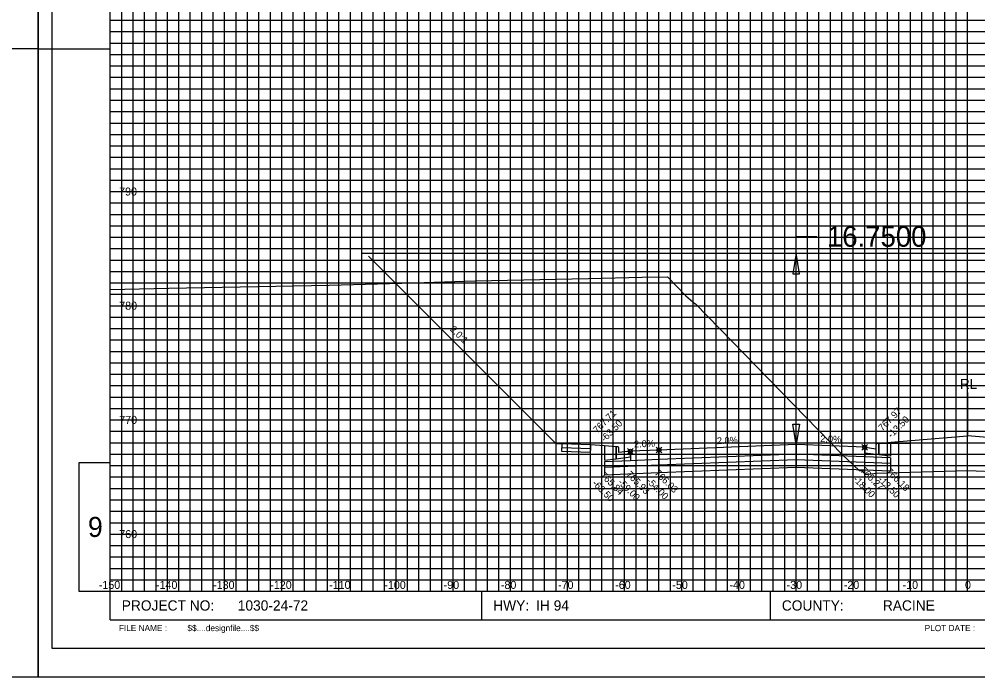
# Model space of a CAD drawing. Extents: x 578243 to 601557, y 174899 to 175559.
# Drawn here: x 600533.9 to 600701.6, y 174898.8 to 175014 of the extents above; entities that cross this region are included whole.
import ezdxf

# ---------------------------------------------------------------- set-up
doc = ezdxf.new("R2010")
doc.units = 0
for name, color, linetype in [('E_PROF_Grid', 7, 'Continuous'), ('E_PROF_GridMin', 7, 'Continuous'), ('P_CRDR_Label', 7, 'Continuous'), ('P_CRDR_Link', 7, 'Continuous'), ('P_E_XS_Ground', 7, 'Continuous'), ('P_RW_SlopeIntercepts', 7, 'Continuous'), ('P_XS_Text', 7, 'Continuous'), ('PLT_Sheet_Border', 7, 'Continuous'), ('PLT_Sheet_Info', 7, 'Continuous')]:
    doc.layers.add(name, color=color, linetype=linetype)

msp = doc.modelspace()

# ---------------------------------------------------------------- linework, layer by layer
at = {"layer": 'E_PROF_Grid'}
for p, q in [((600559.84, 174913.8), (600559.84, 175108.8)), ((600569.84, 174913.8), (600569.84, 175108.8)), ((600579.84, 174913.8), (600579.84, 175108.8)), ((600589.84, 174913.8), (600589.84, 175108.8)), ((600599.84, 174913.8), (600599.84, 175108.8)), ((600609.84, 174913.8), (600609.84, 175108.8)), ((600619.84, 174913.8), (600619.84, 175108.8)), ((600629.84, 174913.8), (600629.84, 175108.8)), ((600639.84, 174913.8), (600639.84, 175108.8)), ((600649.84, 174913.8), (600649.84, 175108.8)), ((600659.84, 174913.8), (600659.84, 175108.8)), ((600669.84, 174913.8), (600669.84, 175108.8)), ((600679.84, 174913.8), (600679.84, 175108.8)), ((600689.84, 174913.8), (600689.84, 175108.8)), ((600699.84, 174913.8), (600699.84, 175108.8)), ((600549.84, 175013.8), (600864.84, 175013.8)), ((600549.84, 175003.8), (600864.84, 175003.8)), ((600549.84, 174993.8), (600864.84, 174993.8)), ((600549.84, 174983.8), (600864.84, 174983.8)), ((600549.84, 174973.8), (600864.84, 174973.8)), ((600549.84, 174963.8), (600864.84, 174963.8)), ((600549.84, 174953.8), (600864.84, 174953.8)), ((600549.84, 174943.8), (600864.84, 174943.8)), ((600549.84, 174933.8), (600864.84, 174933.8)), ((600549.84, 174923.8), (600864.84, 174923.8))]:
    msp.add_line(p, q, dxfattribs=at)
at = {"layer": 'E_PROF_GridMin'}
for p, q in [((600551.84, 174913.8), (600551.84, 175108.8)), ((600553.84, 174913.8), (600553.84, 175108.8)), ((600555.84, 174913.8), (600555.84, 175108.8)), ((600557.84, 174913.8), (600557.84, 175108.8)), ((600561.84, 174913.8), (600561.84, 175108.8)), ((600563.84, 174913.8), (600563.84, 175108.8)), ((600565.84, 174913.8), (600565.84, 175108.8)), ((600567.84, 174913.8), (600567.84, 175108.8)), ((600571.84, 174913.8), (600571.84, 175108.8)), ((600573.84, 174913.8), (600573.84, 175108.8)), ((600575.84, 174913.8), (600575.84, 175108.8)), ((600577.84, 174913.8), (600577.84, 175108.8)), ((600581.84, 174913.8), (600581.84, 175108.8)), ((600583.84, 174913.8), (600583.84, 175108.8)), ((600585.84, 174913.8), (600585.84, 175108.8)), ((600587.84, 174913.8), (600587.84, 175108.8)), ((600591.84, 174913.8), (600591.84, 175108.8)), ((600593.84, 174913.8), (600593.84, 175108.8)), ((600595.84, 174913.8), (600595.84, 175108.8)), ((600597.84, 174913.8), (600597.84, 175108.8)), ((600601.84, 174913.8), (600601.84, 175108.8)), ((600603.84, 174913.8), (600603.84, 175108.8)), ((600605.84, 174913.8), (600605.84, 175108.8)), ((600607.84, 174913.8), (600607.84, 175108.8)), ((600611.84, 174913.8), (600611.84, 175108.8)), ((600613.84, 174913.8), (600613.84, 175108.8)), ((600615.84, 174913.8), (600615.84, 175108.8)), ((600617.84, 174913.8), (600617.84, 175108.8)), ((600621.84, 174913.8), (600621.84, 175108.8)), ((600623.84, 174913.8), (600623.84, 175108.8)), ((600625.84, 174913.8), (600625.84, 175108.8)), ((600627.84, 174913.8), (600627.84, 175108.8)), ((600631.84, 174913.8), (600631.84, 175108.8)), ((600633.84, 174913.8), (600633.84, 175108.8)), ((600635.84, 174913.8), (600635.84, 175108.8)), ((600637.84, 174913.8), (600637.84, 175108.8)), ((600641.84, 174913.8), (600641.84, 175108.8)), ((600643.84, 174913.8), (600643.84, 175108.8)), ((600645.84, 174913.8), (600645.84, 175108.8)), ((600647.84, 174913.8), (600647.84, 175108.8)), ((600651.84, 174913.8), (600651.84, 175108.8)), ((600653.84, 174913.8), (600653.84, 175108.8)), ((600655.84, 174913.8), (600655.84, 175108.8)), ((600657.84, 174913.8), (600657.84, 175108.8)), ((600661.84, 174913.8), (600661.84, 175108.8)), ((600663.84, 174913.8), (600663.84, 175108.8)), ((600665.84, 174913.8), (600665.84, 175108.8)), ((600667.84, 174913.8), (600667.84, 175108.8)), ((600671.84, 174913.8), (600671.84, 175108.8)), ((600673.84, 174913.8), (600673.84, 175108.8)), ((600675.84, 174913.8), (600675.84, 175108.8)), ((600677.84, 174913.8), (600677.84, 175108.8)), ((600681.84, 174913.8), (600681.84, 175108.8)), ((600683.84, 174913.8), (600683.84, 175108.8)), ((600685.84, 174913.8), (600685.84, 175108.8)), ((600687.84, 174913.8), (600687.84, 175108.8)), ((600691.84, 174913.8), (600691.84, 175108.8)), ((600693.84, 174913.8), (600693.84, 175108.8)), ((600695.84, 174913.8), (600695.84, 175108.8)), ((600697.84, 174913.8), (600697.84, 175108.8)), ((600549.84, 175011.8), (600864.84, 175011.8)), ((600549.84, 175009.8), (600864.84, 175009.8)), ((600549.84, 175007.8), (600864.84, 175007.8)), ((600549.84, 175005.8), (600864.84, 175005.8)), ((600549.84, 175001.8), (600864.84, 175001.8)), ((600549.84, 174999.8), (600864.84, 174999.8)), ((600549.84, 174997.8), (600864.84, 174997.8)), ((600549.84, 174995.8), (600864.84, 174995.8)), ((600549.84, 174991.8), (600864.84, 174991.8)), ((600549.84, 174989.8), (600864.84, 174989.8)), ((600549.84, 174987.8), (600864.84, 174987.8)), ((600549.84, 174985.8), (600864.84, 174985.8)), ((600549.84, 174981.8), (600864.84, 174981.8)), ((600549.84, 174979.8), (600864.84, 174979.8)), ((600549.84, 174977.8), (600864.84, 174977.8)), ((600549.84, 174975.8), (600864.84, 174975.8)), ((600549.84, 174971.8), (600864.84, 174971.8)), ((600549.84, 174969.8), (600864.84, 174969.8)), ((600549.84, 174967.8), (600864.84, 174967.8)), ((600549.84, 174965.8), (600864.84, 174965.8)), ((600549.84, 174961.8), (600864.84, 174961.8)), ((600549.84, 174959.8), (600864.84, 174959.8)), ((600549.84, 174957.8), (600864.84, 174957.8)), ((600549.84, 174955.8), (600864.84, 174955.8)), ((600549.84, 174951.8), (600864.84, 174951.8)), ((600549.84, 174949.8), (600864.84, 174949.8)), ((600549.84, 174947.8), (600864.84, 174947.8)), ((600549.84, 174945.8), (600864.84, 174945.8)), ((600549.84, 174941.8), (600864.84, 174941.8)), ((600549.84, 174939.8), (600864.84, 174939.8)), ((600549.84, 174937.8), (600864.84, 174937.8)), ((600549.84, 174935.8), (600864.84, 174935.8)), ((600549.84, 174931.8), (600864.84, 174931.8)), ((600549.84, 174929.8), (600864.84, 174929.8)), ((600549.84, 174927.8), (600864.84, 174927.8)), ((600549.84, 174925.8), (600864.84, 174925.8)), ((600549.84, 174921.8), (600864.84, 174921.8)), ((600549.84, 174919.8), (600864.84, 174919.8)), ((600549.84, 174917.8), (600864.84, 174917.8)), ((600549.84, 174915.8), (600864.84, 174915.8)), ((600537.19, 174898.8), (600537.19, 174908.8)), ((600527.19, 174898.8), (600537.19, 174898.8))]:
    msp.add_line(p, q, dxfattribs=at)
at = {"layer": 'P_CRDR_Label'}
for points in [[(600699.84, 174948.61), (600699.84, 174940.99)], [(600640.35, 174937.82), (600641.34, 174938.81)], [(600640.35, 174938.81), (600641.34, 174937.82)], [(600645.35, 174938.02), (600646.34, 174939.01)], [(600645.35, 174939.01), (600646.34, 174938.02)], [(600681.35, 174938.5), (600682.34, 174939.49)], [(600681.35, 174939.49), (600682.34, 174938.5)]]:
    msp.add_lwpolyline(points, dxfattribs=at)
for centre in [(600645.84, 174938.52), (600681.84, 174939), (600640.84, 174938.32)]:
    msp.add_circle(centre, 0.35, dxfattribs=at)
at = {"layer": 'P_CRDR_Link'}
msp.add_line((600594.99, 174972.46), (600627.84, 174939.61), dxfattribs=at)
for points in [[(600684.34, 174939.75), (600699.84, 174940.99)], [(600684.34, 174939.75), (600699.84, 174940.99)], [(600715.34, 174939.75), (600699.84, 174940.99)], [(600715.34, 174939.75), (600699.84, 174940.99)], [(600628.84, 174939.58), (600627.84, 174939.61)], [(600628.84, 174939.58), (600627.84, 174939.61)], [(600633.84, 174939.43), (600628.84, 174939.58)], [(600633.84, 174939.43), (600628.84, 174939.58)], [(600628.84, 174939.58), (600628.85, 174938.91)], [(600633.84, 174938.76), (600628.85, 174938.91)], [(600628.85, 174938.25), (600628.85, 174938.91)], [(600633.84, 174938.76), (600633.83, 174938.1)], [(600636.34, 174939.23), (600633.84, 174939.43)], [(600636.34, 174939.23), (600633.84, 174939.43)], [(600633.84, 174939.43), (600633.84, 174938.76)], [(600638.34, 174939.07), (600636.34, 174939.23)], [(600636.34, 174939.23), (600636.34, 174936.75)], [(600636.34, 174939.23), (600636.34, 174936.75)], [(600636.34, 174939.23), (600636.34, 174936.75)], [(600638.66, 174939.07), (600638.34, 174939.07)], [(600638.66, 174939.07), (600638.34, 174939.07)], [(600638.34, 174939.07), (600638.34, 174937)], [(600638.34, 174937), (600638.34, 174939.07)], [(600638.74, 174939.02), (600638.66, 174939.07)], [(600638.74, 174939.02), (600638.66, 174939.07)], [(600638.8, 174938.91), (600638.74, 174939.02)], [(600638.8, 174938.91), (600638.74, 174939.02)], [(600638.83, 174938.75), (600638.8, 174938.91)], [(600638.83, 174938.75), (600638.8, 174938.91)], [(600669.84, 174939.48), (600645.84, 174938.52)], [(600681.84, 174939), (600669.84, 174939.48)], [(600669.84, 174939.48), (600669.84, 174937.81)], [(600669.84, 174939.48), (600669.84, 174937.81)], [(600681.84, 174939), (600683.84, 174938.75)], [(600681.84, 174939), (600683.84, 174938.75)], [(600681.84, 174938), (600681.84, 174939)], [(600681.84, 174939), (600681.84, 174937.33)], [(600683.84, 174938.75), (600683.85, 174939.43)], [(600683.84, 174938.75), (600683.85, 174939.43)], [(600683.85, 174939.43), (600683.88, 174939.59)], [(600683.85, 174939.43), (600683.88, 174939.59)], [(600683.88, 174939.59), (600683.94, 174939.7)], [(600683.88, 174939.59), (600683.94, 174939.7)], [(600683.94, 174939.7), (600684.02, 174939.75)], [(600683.94, 174939.7), (600684.02, 174939.75)], [(600684.02, 174939.75), (600684.34, 174939.75)], [(600684.02, 174939.75), (600684.34, 174939.75)], [(600684.34, 174939.75), (600684.34, 174937.68)], [(600684.34, 174939.75), (600686.34, 174939.73)], [(600684.34, 174937.68), (600684.34, 174939.75)], [(600686.34, 174939.73), (600686.34, 174937.43)], [(600686.34, 174939.73), (600686.34, 174937.43)], [(600686.34, 174939.73), (600686.34, 174937.43)], [(600686.34, 174939.73), (600689.84, 174939.7)], [(600686.34, 174939.73), (600689.84, 174939.7)], [(600633.83, 174938.1), (600628.85, 174938.25)], [(600638.34, 174937), (600640.84, 174937.32)], [(600638.34, 174937), (600640.84, 174937.32)], [(600638.84, 174938.07), (600638.83, 174938.75)], [(600638.84, 174938.07), (600638.83, 174938.75)], [(600640.84, 174938.32), (600638.84, 174938.07)], [(600640.84, 174938.32), (600638.84, 174938.07)], [(600645.84, 174938.52), (600640.84, 174938.32)], [(600640.84, 174938.32), (600640.84, 174936.65)], [(600640.84, 174937.32), (600640.84, 174938.32)], [(600645.84, 174938.52), (600645.84, 174936.85)], [(600645.84, 174938.52), (600645.84, 174936.85)], [(600669.84, 174937.81), (600645.84, 174936.85)], [(600681.84, 174937.33), (600669.84, 174937.81)], [(600669.84, 174937.81), (600669.84, 174936.81)], [(600669.84, 174937.81), (600669.84, 174936.81)], [(600684.34, 174937.68), (600681.84, 174938)], [(600684.34, 174937.68), (600681.84, 174938)], [(600686.34, 174937.15), (600681.84, 174937.33)], [(600686.34, 174937.43), (600684.34, 174937.68)], [(600686.34, 174937.15), (600686.34, 174936.15)], [(600636.34, 174936.75), (600638.34, 174937)], [(600640.84, 174936.65), (600636.34, 174936.47)], [(600636.34, 174936.47), (600636.34, 174935.47)], [(600645.84, 174935.85), (600636.34, 174935.47)], [(600636.34, 174935.47), (600636.34, 174934.14)], [(600645.84, 174936.85), (600640.84, 174936.65)], [(600645.84, 174936.85), (600645.84, 174935.85)], [(600645.84, 174936.85), (600645.84, 174935.85)], [(600669.84, 174936.81), (600645.84, 174935.85)], [(600645.84, 174935.85), (600645.84, 174934.52)], [(600645.84, 174935.85), (600645.84, 174934.52)], [(600669.84, 174935.48), (600645.84, 174934.52)], [(600686.34, 174936.15), (600669.84, 174936.81)], [(600669.84, 174936.81), (600669.84, 174935.48)], [(600669.84, 174936.81), (600669.84, 174935.48)], [(600686.34, 174934.82), (600669.84, 174935.48)], [(600686.34, 174936.15), (600686.34, 174934.82)], [(600645.84, 174934.52), (600636.34, 174934.14)]]:
    msp.add_lwpolyline(points, dxfattribs=at)
at = {"layer": 'P_E_XS_Ground'}
msp.add_lwpolyline([(600549.84, 174966.63), (600560.06, 174966.86), (600588.16, 174967.38), (600602.92, 174967.81), (600613.68, 174968.14), (600633.52, 174968.55), (600642.91, 174968.77), (600647.33, 174968.85), (600650.52, 174965.53), (600652.19, 174964.15), (600652.25, 174964.1), (600677.97, 174937.69), (600680.9, 174934.91), (600680.9, 174934.91), (600681.32, 174934.91), (600681.9, 174934.24), (600683.9, 174934.49), (600687.84, 174934.6), (600699.84, 174934.95), (600711.84, 174934.47)], dxfattribs=at)
at = {"layer": 'P_RW_SlopeIntercepts'}
for p, q in [((600669.84, 174975.9), (600673.44, 174975.9)), ((600669.84, 174939.48), (600669.84, 174975.9)), ((600593.84, 174972.98), (600829.84, 174972.98)), ((600669.84, 174972.98), (600669.24, 174969.38)), ((600670.44, 174969.38), (600669.84, 174972.98)), ((600669.24, 174969.38), (600670.44, 174969.38)), ((600669.24, 174943.08), (600670.44, 174943.08)), ((600669.84, 174939.48), (600669.24, 174943.08)), ((600670.44, 174943.08), (600669.84, 174939.48))]:
    msp.add_line(p, q, dxfattribs=at)
at = {"layer": 'PLT_Sheet_Border'}
for points in [[(600197.19, 174898.8), (600537.19, 174898.8), (600537.19, 175118.8), (600197.19, 175118.8)], [(600537.19, 174898.8), (600877.19, 174898.8), (600877.19, 175118.8), (600537.19, 175118.8)], [(600539.59, 174903.8), (600870.59, 174903.8), (600870.59, 175113.8), (600539.59, 175113.8)]]:
    msp.add_lwpolyline(points, close=True, dxfattribs=at)
at = {"layer": 'PLT_Sheet_Info'}
for p, q in [((600549.84, 174908.8), (600549.84, 175108.8)), ((600537.19, 175003.8), (600537.19, 175013.8)), ((600537.19, 175003.8), (600537.19, 175013.8)), ((600537.19, 175008.8), (600524.84, 175008.8)), ((600537.19, 175008.8), (600549.84, 175008.8)), ((600549.84, 174913.8), (600864.84, 174913.8)), ((600614.84, 174908.8), (600614.84, 174913.8)), ((600665.34, 174908.8), (600665.34, 174913.8)), ((600537.19, 174898.8), (600537.19, 174908.8)), ((600549.84, 174908.8), (600864.84, 174908.8)), ((600537.19, 174898.8), (600547.19, 174898.8))]:
    msp.add_line(p, q, dxfattribs=at)
msp.add_lwpolyline([(600549.84, 174936.3), (600544.34, 174936.3), (600544.34, 174913.8), (600549.84, 174913.8)], close=True, dxfattribs=at)

# ---------------------------------------------------------------- texts
at = {"layer": 'P_CRDR_Label'}
for s, rotation, p in [('2.0:1', 315.8532, (600609.19, 174959.54)), ('767.97', 45, (600684.93, 174941.77)), ('767.71', 45, (600635.03, 174941.38)), ('-13.50', 45, (600686.52, 174940.54)), ('-63.50', 45, (600636.34, 174939.86)), ('2.0%', 2.2906, (600656, 174939.54)), ('2.0%', 357.7094, (600674.05, 174939.93)), ('2.0%', 2.2906, (600641.5, 174938.96)), ('766.27', 315, (600680.99, 174934.85)), ('766.18', 315, (600685.49, 174934.67)), ('765.84', 315, (600635.49, 174933.99)), ('765.93', 315, (600640.02, 174934.14)), ('766.03', 315, (600644.99, 174934.37)), ('-63.50', 315, (600634.08, 174932.58)), ('-59.00', 315, (600638.58, 174932.76)), ('-54.00', 315, (600643.58, 174932.96)), ('-18.00', 315, (600679.73, 174933.29)), ('-13.50', 315, (600684.08, 174933.26))]:
    msp.add_text(s, height=1.2, rotation=rotation, dxfattribs=at).set_placement(p)
msp.add_text('RL', height=1.75, dxfattribs=at).set_placement((600698.52, 174949.24))
at = {"layer": 'P_RW_SlopeIntercepts'}
msp.add_text('16.7500', height=3.6, dxfattribs=at).set_placement((600675.24, 174974.13))
at = {"layer": 'P_XS_Text'}
for s, p in [('790', (600551.38, 174983.1)), ('780', (600551.4, 174963.1)), ('770', (600551.4, 174943.1)), ('760', (600551.4, 174923.1)), ('-150', (600547.83, 174914.2)), ('-140', (600557.83, 174914.2)), ('-130', (600567.83, 174914.2)), ('-120', (600577.83, 174914.2)), ('-110', (600588.13, 174914.2)), ('-100', (600597.79, 174914.2)), ('-90', (600608.17, 174914.2)), ('-80', (600618.18, 174914.2)), ('-70', (600628.18, 174914.2)), ('-60', (600638.18, 174914.2)), ('-50', (600648.18, 174914.2)), ('-40', (600658.18, 174914.2)), ('-30', (600668.18, 174914.2)), ('-20', (600678.18, 174914.2)), ('-10', (600688.47, 174914.2)), ('0', (600699.39, 174914.2)), ('0', (600699.39, 174914.2))]:
    msp.add_text(s, height=1.4, rotation=360, dxfattribs=at).set_placement(p)
at = {"layer": 'PLT_Sheet_Info'}
for s, height, p in [('9', 3.5, (600545.92, 174923.3)), ('PROJECT NO:', 1.8, (600551.84, 174910.4)), ('1030-24-72             ', 1.8, (600572.14, 174910.4)), ('HWY:', 1.8, (600616.84, 174910.4)), ('IH 94               ', 1.8, (600624.34, 174910.4)), ('COUNTY:', 1.8, (600667.34, 174910.4)), ('       RACINE       ', 1.8, (600680.34, 174910.4)), ('FILE NAME :', 1.08, (600551.34, 174906.8))]:
    msp.add_text(s, height=height, dxfattribs=at).set_placement(p)
for s, p in [('$$....designfile....$$', (600563.34, 174906.8)), ('PLOT DATE :', (600692.34, 174906.8))]:
    msp.add_text(s, height=1.08, rotation=360, dxfattribs=at).set_placement(p)

doc.saveas('drawing.dxf')
